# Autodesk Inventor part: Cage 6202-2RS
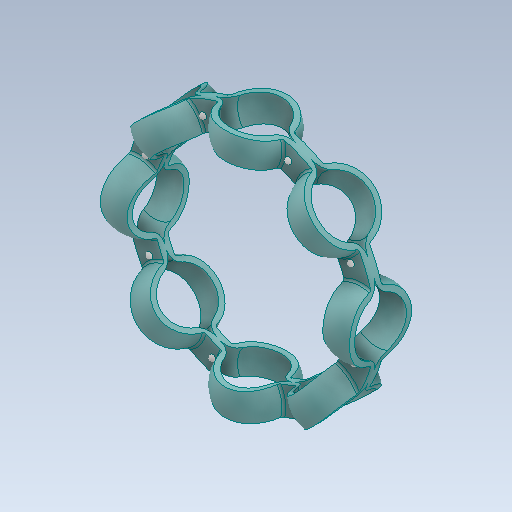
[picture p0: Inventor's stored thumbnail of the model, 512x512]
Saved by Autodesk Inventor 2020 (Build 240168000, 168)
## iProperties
Created: 2001-06
Part Number: Cage 6202-2RS
Material: Générique
Document SubType Name: Modeling
Designer: Bruno
Density: 1 g/cm^3
Appearance: Par défaut
Author: Bruno
Sending System: SolidWorks 2011
Last Author: frederic
Last Saved: 2012-02-20
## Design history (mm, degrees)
feature "Bossage-Symétrie1"
node "Solide1"
